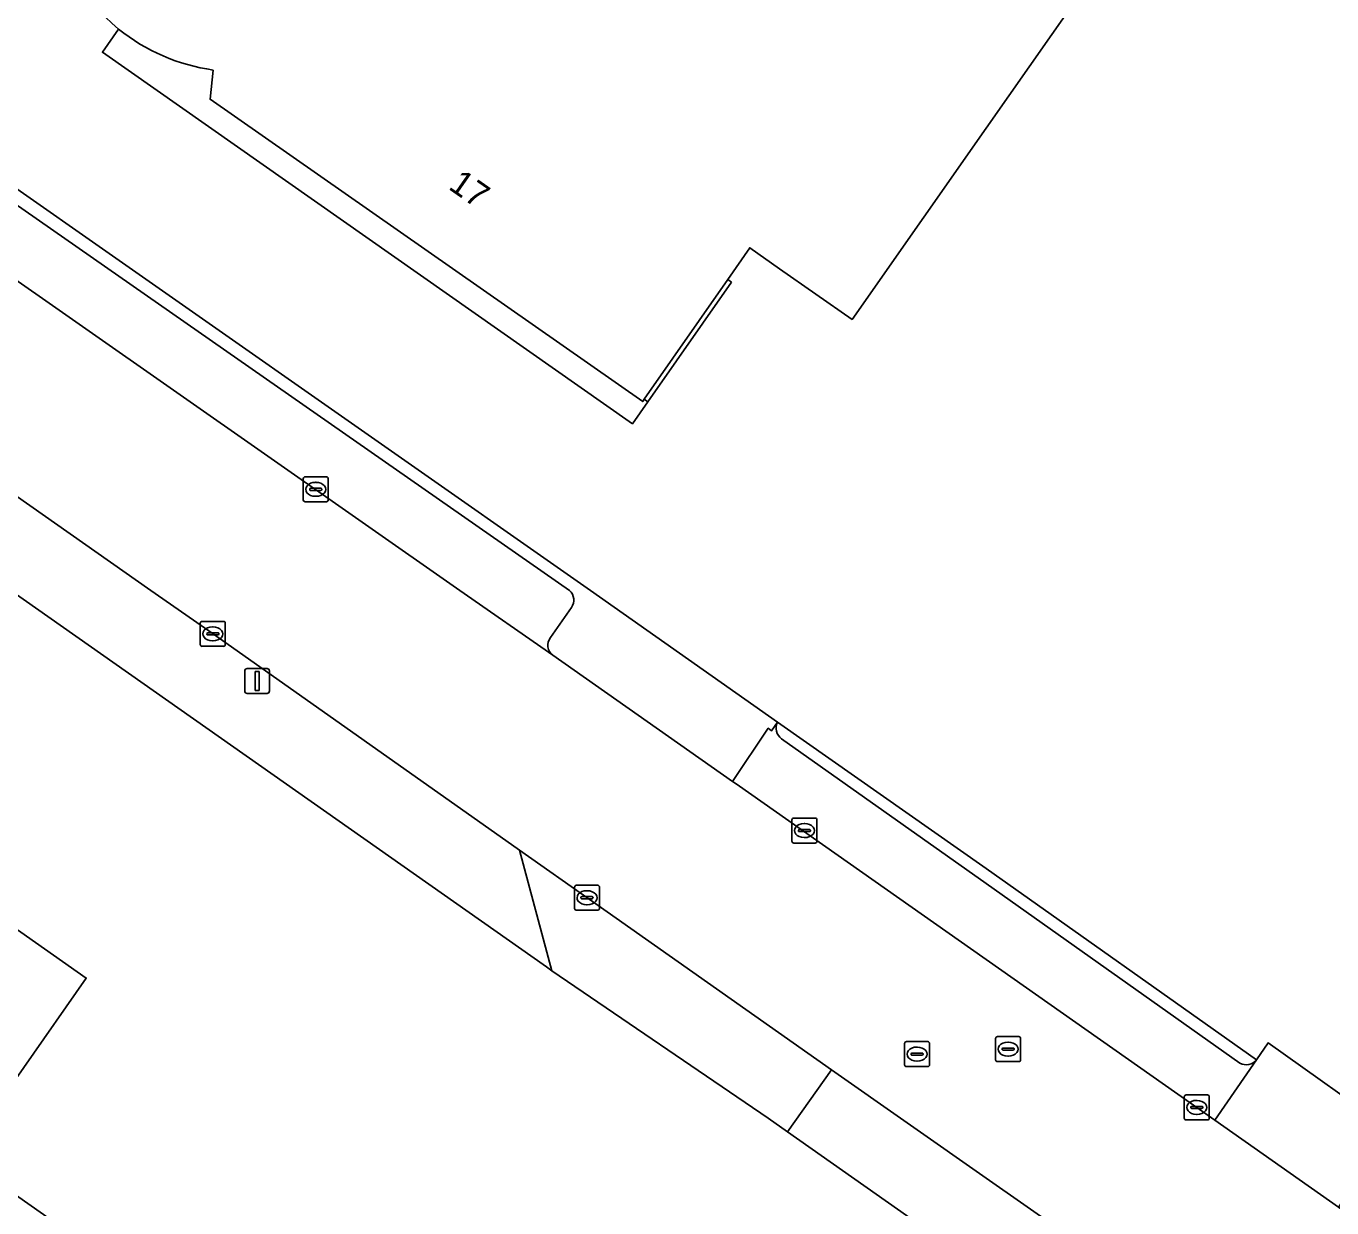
# Model space of a CAD drawing. Extents: x 155018 to 156648, y 383979 to 385733.
# Drawn here: x 155461.5 to 155513.9, y 384975.3 to 385022.6 of the extents above; entities that cross this region are included whole.
import ezdxf

# ---------------------------------------------------------------- set-up
doc = ezdxf.new("R2010")
doc.units = 0
for name, color, linetype in [('IMGEO_Erf', 7, 'Continuous'), ('IMGEO_Hek', 7, 'Continuous'), ('IMGEO_Kolk', 7, 'Continuous'), ('IMGEO_Lichtmast', 7, 'Continuous'), ('IMGEO_Pand', 7, 'Continuous'), ('IMGEO_Pand_nummerreeks', 7, 'Continuous'), ('IMGEO_Pand_overbouw', 7, 'Continuous'), ('IMGEO_Parkeervlak_open', 7, 'Continuous'), ('IMGEO_Rijbaan_lokaal_gesloten', 7, 'Continuous'), ('IMGEO_Rioolput', 7, 'Continuous'), ('IMGEO_Voetpad_open', 7, 'Continuous')]:
    doc.layers.add(name, color=color, linetype=linetype)

msp = doc.modelspace()

# ---------------------------------------------------------------- linework, layer by layer
at = {"layer": 'IMGEO_Erf'}
for points in [[(155466.604, 385035.357), (155465.725, 385035.996), (155472.35, 385045.109), (155477.04, 385041.699), (155478.294, 385040.788), (155481.22, 385044.812), (155485.315, 385041.942), (155500, 385031.649), (155506.174, 385027.322), (155500, 385018.512), (155497.5, 385014.945), (155494.63, 385010.85), (155491.727, 385012.882), (155490.53, 385013.72), (155489.645, 385012.449), (155486.305, 385007.654)], [(155486.305, 385007.654), (155486.24, 385007.56), (155468.91, 385019.67), (155469.034, 385020.841)], [(155457.525, 385018.63), (155458.619, 385017.864), (155484.145, 385000), (155491.64, 384994.721), (155500, 384988.865), (155510.83, 384981.203), (155511.294, 384981.88), (155516.258, 384978.35), (155515.775, 384977.663), (155553.601, 384951.142), (155553.738, 384951.046), (155554.058, 384951.47), (155560.497, 384946.89), (155560.229, 384946.497), (155580.857, 384931.994), (155586.597, 384927.958), (155607.46, 384913.427), (155617.317, 384906.512), (155620.874, 384904.014), (155651.48, 384882.509)], [(155645.703, 384870.176), (155613.715, 384892.628), (155600.657, 384901.793), (155582.308, 384914.778), (155574.917, 384919.981), (155570.133, 384923.483), (155539.854, 384944.743), (155535.161, 384948.038), (155534.984, 384948.163), (155531.101, 384950.889), (155530.5, 384951.311), (155510.828, 384965.124), (155506.264, 384968.328), (155505.588, 384968.803), (155501.395, 384971.747), (155500, 384972.727), (155492.047, 384978.311), (155491.266, 384978.86), (155482.605, 384984.76), (155482.381, 384984.92), (155460.927, 385000), (155450.653, 385007.222)]]:
    msp.add_lwpolyline(points, dxfattribs=at)
msp.add_lwpolyline([(155437.272, 384901.403), (155412.162, 384919.023), (155417.316, 384926.358), (155404.257, 384935.52), (155429.931, 384972.307), (155422.839, 384977.259), (155438.817, 385000), (155439.816, 385001.422), (155441.823, 385000), (155445.207, 384997.603), (155444.284, 384997.18), (155444.973, 384993.255), (155452.396, 384994.446), (155452.453, 384994.103), (155450.711, 384993.78), (155463.948, 384984.474), (155458.937, 384977.31), (155471.068, 384968.794), (155464.079, 384958.829), (155473.162, 384952.461)], close=True, dxfattribs=at)
for centre, radius, start, end in [((155470.091, 385028.479), 7.71, 149.5885, 231.0569), ((155470.099, 385028.492), 7.725, 231.0666, 262.0735)]:
    msp.add_arc(centre, radius, start, end, dxfattribs=at)
at = {"layer": 'IMGEO_Hek'}
msp.add_lwpolyline([(155486.305, 385007.654), (155486.445, 385007.555)], dxfattribs=at)
at = {"layer": 'IMGEO_Kolk'}
for p, q in [((155472.641, 385003.622), (155472.641, 385004.474)), ((155472.716, 385004.548), (155473.568, 385004.548)), ((155473.129, 385004.328), (155473.154, 385004.328)), ((155473.642, 385004.474), (155473.642, 385003.622)), ((155472.9, 385004.042), (155472.9, 385004.054)), ((155473.338, 385004.005), (155472.94, 385004.005)), ((155472.943, 385004.091), (155473.341, 385004.091)), ((155473.384, 385004.054), (155473.384, 385004.042)), ((155473.568, 385003.548), (155472.716, 385003.548)), ((155473.152, 385003.768), (155473.127, 385003.768)), ((155468.518, 384997.834), (155468.518, 384998.686)), ((155468.593, 384998.76), (155469.445, 384998.76)), ((155469.519, 384998.686), (155469.519, 384997.834)), ((155468.777, 384998.254), (155468.777, 384998.266)), ((155469.215, 384998.217), (155468.817, 384998.217)), ((155468.82, 384998.303), (155469.218, 384998.303)), ((155469.006, 384998.54), (155469.031, 384998.54)), ((155469.261, 384998.266), (155469.261, 384998.254)), ((155469.445, 384997.76), (155468.593, 384997.76)), ((155469.029, 384997.98), (155469.004, 384997.98)), ((155492.218, 384989.955), (155492.218, 384990.807)), ((155492.293, 384990.881), (155493.145, 384990.881)), ((155493.219, 384990.807), (155493.219, 384989.955)), ((155492.477, 384990.375), (155492.477, 384990.387)), ((155492.915, 384990.338), (155492.517, 384990.338)), ((155492.52, 384990.424), (155492.918, 384990.424)), ((155492.706, 384990.661), (155492.731, 384990.661)), ((155492.961, 384990.387), (155492.961, 384990.375)), ((155493.145, 384989.881), (155492.293, 384989.881)), ((155492.729, 384990.101), (155492.704, 384990.101)), ((155483.509, 384987.266), (155483.509, 384988.118)), ((155483.584, 384988.192), (155484.436, 384988.192)), ((155484.51, 384988.118), (155484.51, 384987.266)), ((155483.768, 384987.686), (155483.768, 384987.698)), ((155484.206, 384987.649), (155483.808, 384987.649)), ((155483.811, 384987.735), (155484.209, 384987.735)), ((155483.997, 384987.972), (155484.022, 384987.972)), ((155484.252, 384987.698), (155484.252, 384987.686)), ((155484.436, 384987.192), (155483.584, 384987.192)), ((155484.02, 384987.412), (155483.995, 384987.412)), ((155507.937, 384978.868), (155507.937, 384979.72)), ((155508.012, 384979.794), (155508.864, 384979.794)), ((155508.938, 384979.72), (155508.938, 384978.868)), ((155508.196, 384979.288), (155508.196, 384979.3)), ((155508.634, 384979.251), (155508.236, 384979.251)), ((155508.239, 384979.337), (155508.637, 384979.337)), ((155508.425, 384979.574), (155508.45, 384979.574)), ((155508.68, 384979.3), (155508.68, 384979.288)), ((155508.864, 384978.794), (155508.012, 384978.794)), ((155508.448, 384979.014), (155508.423, 384979.014))]:
    msp.add_line(p, q, dxfattribs=at)
for points in [[(155472.641, 385003.622), (155472.641, 385004.474)], [(155472.716, 385004.548), (155473.568, 385004.548)], [(155473.642, 385004.474), (155473.642, 385003.622)], [(155473.568, 385003.548), (155472.716, 385003.548)], [(155468.518, 384997.834), (155468.518, 384998.686)], [(155468.593, 384998.76), (155469.445, 384998.76)], [(155469.519, 384998.686), (155469.519, 384997.834)], [(155469.445, 384997.76), (155468.593, 384997.76)], [(155492.218, 384989.955), (155492.218, 384990.807)], [(155492.293, 384990.881), (155493.145, 384990.881)], [(155493.219, 384990.807), (155493.219, 384989.955)], [(155493.145, 384989.881), (155492.293, 384989.881)], [(155483.509, 384987.266), (155483.509, 384988.118)], [(155483.584, 384988.192), (155484.436, 384988.192)], [(155484.51, 384988.118), (155484.51, 384987.266)], [(155484.436, 384987.192), (155483.584, 384987.192)], [(155507.937, 384978.868), (155507.937, 384979.72)], [(155508.012, 384979.794), (155508.864, 384979.794)], [(155508.938, 384979.72), (155508.938, 384978.868)], [(155508.864, 384978.794), (155508.012, 384978.794)]]:
    msp.add_lwpolyline(points, dxfattribs=at)
for centre, radius, start, end in [((155472.718, 385004.472), 0.0765, 91.552, 178.448), ((155472.718, 385004.472), 0.0765, 91.552, 178.448), ((155473.566, 385004.472), 0.0765, 1.552, 88.448), ((155473.566, 385004.472), 0.0765, 1.552, 88.448), ((155472.94, 385004.051), 0.0403, 85.8775, 175.7526), ((155472.937, 385004.041), 0.0366, 178.938, 274.7102), ((155473.341, 385004.048), 0.043, 264.8664, 352.4533), ((155473.345, 385004.053), 0.0386, 1.7309, 96.639), ((155472.718, 385003.624), 0.0765, 181.552, 268.448), ((155472.718, 385003.624), 0.0765, 181.552, 268.448), ((155473.566, 385003.624), 0.0765, 271.552, 358.448), ((155473.566, 385003.624), 0.0765, 271.552, 358.448), ((155468.595, 384998.684), 0.0765, 91.552, 178.448), ((155468.595, 384998.684), 0.0765, 91.552, 178.448), ((155469.443, 384998.684), 0.0765, 1.552, 88.448), ((155469.443, 384998.684), 0.0765, 1.552, 88.448), ((155468.817, 384998.263), 0.0403, 85.8775, 175.7526), ((155468.814, 384998.253), 0.0366, 178.938, 274.7102), ((155469.218, 384998.26), 0.043, 264.8664, 352.4533), ((155469.222, 384998.265), 0.0386, 1.7309, 96.639), ((155468.595, 384997.836), 0.0765, 181.552, 268.448), ((155468.595, 384997.836), 0.0765, 181.552, 268.448), ((155469.443, 384997.836), 0.0765, 271.552, 358.448), ((155469.443, 384997.836), 0.0765, 271.552, 358.448), ((155492.295, 384990.805), 0.0765, 91.552, 178.448), ((155492.295, 384990.805), 0.0765, 91.552, 178.448), ((155493.143, 384990.805), 0.0765, 1.552, 88.448), ((155493.143, 384990.805), 0.0765, 1.552, 88.448), ((155492.517, 384990.384), 0.0403, 85.8775, 175.7526), ((155492.514, 384990.374), 0.0366, 178.938, 274.7102), ((155492.918, 384990.381), 0.043, 264.8664, 352.4533), ((155492.922, 384990.386), 0.0386, 1.7309, 96.639), ((155492.295, 384989.957), 0.0765, 181.552, 268.448), ((155492.295, 384989.957), 0.0765, 181.552, 268.448), ((155493.143, 384989.957), 0.0765, 271.552, 358.448), ((155493.143, 384989.957), 0.0765, 271.552, 358.448), ((155483.586, 384988.116), 0.0765, 91.552, 178.448), ((155483.586, 384988.116), 0.0765, 91.552, 178.448), ((155484.434, 384988.116), 0.0765, 1.552, 88.448), ((155484.434, 384988.116), 0.0765, 1.552, 88.448), ((155483.808, 384987.695), 0.0403, 85.8775, 175.7526), ((155483.805, 384987.685), 0.0366, 178.938, 274.7102), ((155484.209, 384987.692), 0.043, 264.8664, 352.4533), ((155484.213, 384987.697), 0.0386, 1.7309, 96.639), ((155483.586, 384987.268), 0.0765, 181.552, 268.448), ((155483.586, 384987.268), 0.0765, 181.552, 268.448), ((155484.434, 384987.268), 0.0765, 271.552, 358.448), ((155484.434, 384987.268), 0.0765, 271.552, 358.448), ((155508.014, 384979.718), 0.0765, 91.552, 178.448), ((155508.014, 384979.718), 0.0765, 91.552, 178.448), ((155508.862, 384979.718), 0.0765, 1.552, 88.448), ((155508.862, 384979.718), 0.0765, 1.552, 88.448), ((155508.236, 384979.297), 0.0403, 85.8775, 175.7526), ((155508.233, 384979.287), 0.0366, 178.938, 274.7102), ((155508.637, 384979.294), 0.043, 264.8664, 352.4533), ((155508.641, 384979.299), 0.0386, 1.7309, 96.639), ((155508.014, 384978.87), 0.0765, 181.552, 268.448), ((155508.014, 384978.87), 0.0765, 181.552, 268.448), ((155508.862, 384978.87), 0.0765, 271.552, 358.448), ((155508.862, 384978.87), 0.0765, 271.552, 358.448)]:
    msp.add_arc(centre, radius, start, end, dxfattribs=at)
for centre, major_axis, ratio, start_param, end_param in [((155473.128, 385004.048), (-0.387, 0.002), 0.722429, 4.712389, 7.853982), ((155473.153, 385004.048), (-0.39, 0.002), 0.717154, 1.570796, 4.712389), ((155469.005, 384998.26), (-0.387, 0.002), 0.722429, 4.712389, 7.853982), ((155469.03, 384998.26), (-0.39, 0.002), 0.717154, 1.570796, 4.712389), ((155492.705, 384990.381), (-0.387, 0.002), 0.722429, 4.712389, 7.853982), ((155492.73, 384990.381), (-0.39, 0.002), 0.717154, 1.570796, 4.712389), ((155483.996, 384987.692), (-0.387, 0.002), 0.722429, 4.712389, 7.853982), ((155484.021, 384987.692), (-0.39, 0.002), 0.717154, 1.570796, 4.712389), ((155508.424, 384979.294), (-0.387, 0.002), 0.722429, 4.712389, 7.853982), ((155508.449, 384979.294), (-0.39, 0.002), 0.717154, 1.570796, 4.712389)]:
    msp.add_ellipse(centre, major_axis=major_axis, ratio=ratio, start_param=start_param, end_param=end_param, dxfattribs=at)
at = {"layer": 'IMGEO_Lichtmast'}
for p, q in [((155470.3, 384995.972), (155470.3, 384996.772)), ((155470.3, 384996.772), (155470.3, 384995.972)), ((155470.4, 384996.872), (155471.19, 384996.872)), ((155471.19, 384996.872), (155470.4, 384996.872)), ((155471.29, 384996.772), (155471.29, 384995.972)), ((155471.29, 384995.972), (155471.29, 384996.772)), ((155471.19, 384995.872), (155470.4, 384995.872)), ((155470.4, 384995.872), (155471.19, 384995.872))]:
    msp.add_line(p, q, dxfattribs=at)
msp.add_lwpolyline([(155470.72, 384996.747), (155470.87, 384996.747), (155470.87, 384995.997), (155470.72, 384995.997), (155470.72, 384996.747)], dxfattribs=at)
for centre, start, end in [((155470.4, 384996.772), 90, 180), ((155470.4, 384996.772), 90, 180), ((155471.19, 384996.772), 0, 90), ((155471.19, 384996.772), 360, 90), ((155470.4, 384995.972), 180, 270), ((155470.4, 384995.972), 180, 270), ((155471.19, 384995.972), 270, 0), ((155471.19, 384995.972), 270, 0)]:
    msp.add_arc(centre, 0.1, start, end, dxfattribs=at)
at = {"layer": 'IMGEO_Pand'}
msp.add_lwpolyline([(155469.034, 385020.841), (155468.91, 385019.67), (155486.24, 385007.56), (155486.305, 385007.654), (155489.645, 385012.449), (155490.53, 385013.72), (155491.727, 385012.882), (155494.63, 385010.85), (155497.5, 385014.945), (155500, 385018.512), (155506.174, 385027.322), (155500, 385031.649), (155485.315, 385041.942), (155481.22, 385044.812), (155478.294, 385040.788), (155477.04, 385041.699), (155472.35, 385045.109), (155465.725, 385035.996), (155466.604, 385035.357)], dxfattribs=at)
msp.add_lwpolyline([(155437.272, 384901.403), (155473.162, 384952.461), (155464.079, 384958.829), (155471.068, 384968.794), (155458.937, 384977.31), (155463.948, 384984.474), (155450.711, 384993.78), (155452.453, 384994.103), (155452.396, 384994.446), (155444.973, 384993.255), (155444.284, 384997.18), (155445.207, 384997.603), (155441.823, 385000), (155439.816, 385001.422), (155438.817, 385000), (155422.839, 384977.259), (155429.931, 384972.307), (155404.257, 384935.52), (155417.316, 384926.358), (155412.162, 384919.023)], close=True, dxfattribs=at)
for centre, radius, start, end in [((155470.091, 385028.479), 7.71, 149.5885, 231.0569), ((155470.099, 385028.492), 7.725, 231.0666, 262.0735)]:
    msp.add_arc(centre, radius, start, end, dxfattribs=at)
at = {"layer": 'IMGEO_Pand_overbouw'}
for points in [[(155465.245, 385022.483), (155464.594, 385021.554), (155485.829, 385006.676), (155486.445, 385007.555), (155489.799, 385012.342)], [(155489.799, 385012.342), (155489.645, 385012.449), (155486.305, 385007.654), (155486.24, 385007.56), (155468.91, 385019.67), (155469.034, 385020.841)]]:
    msp.add_lwpolyline(points, dxfattribs=at)
msp.add_arc((155470.099, 385028.492), 7.725, 231.0666, 262.0735, dxfattribs=at)
at = {"layer": 'IMGEO_Parkeervlak_open'}
for points in [[(155483.311, 385000), (155458.31, 385017.422)], [(155456.1, 385015.949), (155478.917, 385000), (155482.635, 384997.401)], [(155482.541, 384998.11), (155483.386, 384999.309)], [(155491.64, 384994.721), (155491.406, 384994.376), (155491.269, 384994.482), (155489.845, 384992.352), (155489.982, 384992.256), (155500, 384985.217), (155509.167, 384978.777), (155510.83, 384981.203)], [(155510.166, 384981.066), (155500, 384988.262), (155491.808, 384994.06)]]:
    msp.add_lwpolyline(points, dxfattribs=at)
for centre, radius, start, end in [((155482.948, 384999.611), 0.532, 325.4056, 46.9834), ((155482.939, 384997.802), 0.503, 142.2366, 232.868), ((155492.106, 384994.488), 0.521, 153.4162, 235.1046), ((155510.418, 384981.523), 0.522, 241.1688, 322.1472)]:
    msp.add_arc(centre, radius, start, end, dxfattribs=at)
at = {"layer": 'IMGEO_Rijbaan_lokaal_gesloten'}
for points in [[(155650.099, 384879.818), (155615.524, 384904.073), (155605.603, 384911.034), (155580.666, 384928.528), (155558.57, 384944.057), (155551.965, 384948.699), (155514.295, 384975.174), (155514.115, 384975.3), (155509.167, 384978.777), (155500, 384985.217), (155489.982, 384992.256), (155489.845, 384992.352), (155482.635, 384997.401), (155478.917, 385000), (155456.1, 385015.949)], [(155452.478, 385009.864), (155466.537, 385000), (155468.855, 384998.374), (155481.303, 384989.599), (155484.226, 384987.538), (155493.798, 384980.798), (155500, 384976.456), (155502.879, 384974.44), (155503.149, 384974.25), (155507.358, 384971.292), (155508.017, 384970.829), (155512.594, 384967.613), (155532.25, 384953.8), (155532.882, 384953.356), (155536.732, 384950.651), (155536.91, 384950.526), (155541.6, 384947.23), (155571.894, 384925.942), (155573.015, 384925.172), (155576.741, 384922.577), (155602.522, 384904.454), (155615.591, 384895.277), (155647.55, 384872.837)]]:
    msp.add_lwpolyline(points, dxfattribs=at)
at = {"layer": 'IMGEO_Rioolput'}
for p, q in [((155496.731, 384981.004), (155496.731, 384981.856)), ((155496.806, 384981.93), (155497.658, 384981.93)), ((155497.732, 384981.856), (155497.732, 384981.004)), ((155500.378, 384981.203), (155500.378, 384982.055)), ((155500.453, 384982.129), (155501.305, 384982.129)), ((155500.866, 384981.909), (155500.891, 384981.909)), ((155501.379, 384982.055), (155501.379, 384981.203)), ((155496.99, 384981.424), (155496.99, 384981.436)), ((155497.428, 384981.387), (155497.03, 384981.387)), ((155497.033, 384981.473), (155497.431, 384981.473)), ((155497.219, 384981.71), (155497.244, 384981.71)), ((155497.474, 384981.436), (155497.474, 384981.424)), ((155500.637, 384981.623), (155500.637, 384981.635)), ((155501.075, 384981.586), (155500.677, 384981.586)), ((155500.68, 384981.672), (155501.078, 384981.672)), ((155500.889, 384981.349), (155500.864, 384981.349)), ((155501.121, 384981.635), (155501.121, 384981.623)), ((155497.658, 384980.93), (155496.806, 384980.93)), ((155497.242, 384981.15), (155497.217, 384981.15)), ((155501.305, 384981.129), (155500.453, 384981.129))]:
    msp.add_line(p, q, dxfattribs=at)
for points in [[(155496.731, 384981.004), (155496.731, 384981.856)], [(155496.806, 384981.93), (155497.658, 384981.93)], [(155497.732, 384981.856), (155497.732, 384981.004)], [(155500.378, 384981.203), (155500.378, 384982.055)], [(155500.453, 384982.129), (155501.305, 384982.129)], [(155501.379, 384982.055), (155501.379, 384981.203)], [(155497.658, 384980.93), (155496.806, 384980.93)], [(155501.305, 384981.129), (155500.453, 384981.129)]]:
    msp.add_lwpolyline(points, dxfattribs=at)
for centre, radius, start, end in [((155496.808, 384981.854), 0.0765, 91.552, 178.448), ((155496.808, 384981.854), 0.0765, 91.552, 178.448), ((155497.656, 384981.854), 0.0765, 1.552, 88.448), ((155497.656, 384981.854), 0.0765, 1.552, 88.448), ((155500.455, 384982.053), 0.0765, 91.552, 178.448), ((155500.455, 384982.053), 0.0765, 91.552, 178.448), ((155501.303, 384982.053), 0.0765, 1.552, 88.448), ((155501.303, 384982.053), 0.0765, 1.552, 88.448), ((155497.03, 384981.433), 0.0403, 85.8775, 175.7526), ((155497.027, 384981.423), 0.0366, 178.938, 274.7102), ((155497.431, 384981.43), 0.043, 264.8664, 352.4533), ((155497.435, 384981.435), 0.0386, 1.7309, 96.639), ((155500.677, 384981.632), 0.0403, 85.8775, 175.7526), ((155500.674, 384981.622), 0.0366, 178.938, 274.7102), ((155501.078, 384981.629), 0.043, 264.8664, 352.4533), ((155501.082, 384981.634), 0.0386, 1.7309, 96.639), ((155496.808, 384981.006), 0.0765, 181.552, 268.448), ((155496.808, 384981.006), 0.0765, 181.552, 268.448), ((155497.656, 384981.006), 0.0765, 271.552, 358.448), ((155497.656, 384981.006), 0.0765, 271.552, 358.448), ((155500.455, 384981.205), 0.0765, 181.552, 268.448), ((155500.455, 384981.205), 0.0765, 181.552, 268.448), ((155501.303, 384981.205), 0.0765, 271.552, 358.448), ((155501.303, 384981.205), 0.0765, 271.552, 358.448)]:
    msp.add_arc(centre, radius, start, end, dxfattribs=at)
for centre, major_axis, ratio, start_param, end_param in [((155500.865, 384981.629), (-0.387, 0.002), 0.722429, 4.712389, 7.853982), ((155500.89, 384981.629), (-0.39, 0.002), 0.717154, 1.570796, 4.712389), ((155497.218, 384981.43), (-0.387, 0.002), 0.722429, 4.712389, 7.853982), ((155497.243, 384981.43), (-0.39, 0.002), 0.717154, 1.570796, 4.712389)]:
    msp.add_ellipse(centre, major_axis=major_axis, ratio=ratio, start_param=start_param, end_param=end_param, dxfattribs=at)
at = {"layer": 'IMGEO_Voetpad_open'}
for points in [[(155484.145, 385000), (155458.619, 385017.864), (155458.31, 385017.422), (155483.311, 385000)], [(155450.653, 385007.222), (155460.927, 385000), (155482.381, 384984.92), (155482.605, 384984.76), (155481.303, 384989.599), (155468.855, 384998.374), (155466.537, 385000), (155452.478, 385009.864)], [(155482.635, 384997.401), (155489.845, 384992.352), (155491.269, 384994.482), (155491.406, 384994.376), (155491.64, 384994.721), (155484.145, 385000)], [(155483.386, 384999.309), (155482.541, 384998.11)], [(155510.83, 384981.203), (155500, 384988.865), (155491.64, 384994.721)], [(155491.808, 384994.06), (155500, 384988.262), (155510.166, 384981.066)]]:
    msp.add_lwpolyline(points, dxfattribs=at)
for points in [[(155493.798, 384980.798), (155484.226, 384987.538), (155481.303, 384989.599), (155482.605, 384984.76), (155491.266, 384978.86), (155492.047, 384978.311)], [(155514.115, 384975.3), (155515.775, 384977.663), (155516.258, 384978.35), (155511.294, 384981.88), (155510.83, 384981.203), (155509.167, 384978.777)], [(155493.798, 384980.798), (155492.047, 384978.311), (155500, 384972.727), (155501.395, 384971.747), (155503.149, 384974.25), (155502.879, 384974.44), (155500, 384976.456)]]:
    msp.add_lwpolyline(points, close=True, dxfattribs=at)
for centre, radius, start, end in [((155482.948, 384999.611), 0.532, 325.4056, 46.9834), ((155482.939, 384997.802), 0.503, 142.2366, 232.868), ((155492.106, 384994.488), 0.521, 153.4162, 235.1046), ((155510.418, 384981.523), 0.522, 241.1688, 322.1472)]:
    msp.add_arc(centre, radius, start, end, dxfattribs=at)

# ---------------------------------------------------------------- texts
at = {"layer": 'IMGEO_Pand_nummerreeks'}
msp.add_text('17', height=1, rotation=325.0546, dxfattribs=at).set_placement((155478.416, 385016.102))

doc.saveas('drawing.dxf')
